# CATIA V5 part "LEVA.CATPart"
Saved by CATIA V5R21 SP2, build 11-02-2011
Part number: LEVA
Bounding box of the stored display mesh (mm): x -5 to 5, y -31.434 to 31.661, z -31.435 to 38.509
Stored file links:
  C:\Users\alberto.delaflor\Desktop\LEVA\LEVA\LEVA.CATPart
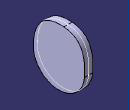
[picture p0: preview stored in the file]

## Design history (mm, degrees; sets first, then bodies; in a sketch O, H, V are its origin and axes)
AxisSystem1: origin (0, 0, 0), X (1, 0, 0), Y (0, 1, 0), Z (0, 0, 1)
Set1
  Sketch1 on YZ plane of AxisSystem1, origin (0, 0, 0), H (0, 1, 0), V (0, 0, 1)
    arc A1 centre (0, 0) radius 31.4354 from (-31.3785, 1.8904) to (31.328, -2.5968) ccw
    spline S1 through (31.328, -2.5968) (15.9834, 36.2774) (6.1848, 38.3859)
    spline S2 through (-31.3785, 1.8904) (-16.9481, 33.5059) (6.1848, 38.3859)
    point P1 (31.328, -2.5968)
    point P2 (-31.3785, 1.8904)
    point P3 (31.328, -2.5968)
    point P4 (-31.3785, 1.8904)
    point P5 (6.1848, 38.3859)
    point P6 (6.1848, 38.3859)
    coincidence: P3 A1, P4 A1, P5 P6, P3 P1, P4 P2
    tangency: S1 A1, S2 A1, S1 S2
  Extract1: ExtractElem face of Pad1 from Sketch1.S1
  Intersect1: ToIntersect1 YZ plane of AxisSystem1, ToIntersect2 Extract1
Body1 (main body)
  Pad1: profile Sketch1, direction (1, 0, 0), length 5, mirrored extent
